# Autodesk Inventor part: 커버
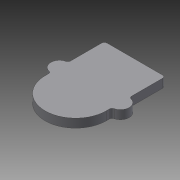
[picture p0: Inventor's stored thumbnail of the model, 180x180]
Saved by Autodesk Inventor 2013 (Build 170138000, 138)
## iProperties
Created: 2024-02
Part Number: 커버
Material: 알루미늄 6061
Document SubType Name: Modeling
Designer: mdu-01
Density: 1 g/cm^3
Author: mdu-01
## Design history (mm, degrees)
sketch "스케치1"
  geometry: L1 (14, -3.702)-(14, -14.074) reference; L2 (-14, -14.074)-(-14, -3.702) reference; L3 (35, 3.761)-(35, 39.612) reference; L4 (32, 42.612)-(-32, 42.612) reference; L5 (-35, 39.612)-(-35, 3.761) reference; L6 (-35, -21.537)-(-35, -25.388) reference; L7 (35, -25.388)-(35, -21.537) reference; C1 r 2.75 at (0, -51.388) reference; C2 r 2.75 at (-35, -8.888) reference; C3 r 2.75 at (35, -8.888) reference; C4 r 2.75 at (0, 33.612) reference; A1 r 18 centre (0, 7.612) between (14, -3.702) and (-14, -3.702) reference; A2 r 18 centre (0, -25.388) between (-14, -14.074) and (14, -14.074) reference; A3 r 3 centre (38, 3.761) between (35, 3.761) and (37.308, 0.842) reference; A4 r 3 centre (32, 39.612) between (35, 39.612) and (32, 42.612) reference; A5 r 3 centre (-32, 39.612) between (-32, 42.612) and (-35, 39.612) reference; A6 r 3 centre (-38, 3.761) between (-37.308, 0.842) and (-35, 3.761) reference; A7 r 10 centre (-35, -8.888) between (-37.308, 0.842) and (-37.308, -18.618) reference; A8 r 3 centre (-38, -21.537) between (-35, -21.537) and (-37.308, -18.618) reference; A9 r 35 centre (0, -25.388) between (-35, -25.388) and (35, -25.388) reference; A10 r 3 centre (38, -21.537) between (37.308, -18.618) and (35, -21.537) reference; A11 r 10 centre (35, -8.888) between (37.308, -18.618) and (37.308, 0.842) reference; 1 further point
extrude "돌출1" new body sketch "스케치1" distance "d0" = 10; taper "d1" = 0 deg
sketch "스케치2"
  geometry: L1 (-15, 7.612)-(-15, -25.388); L2 (15, 7.612)-(15, -25.388); A1 r 15 centre (0, -25.388) between (-15, -25.388) and (15, -25.388); A2 r 15 centre (0, 7.612) between (15, 7.612) and (-15, 7.612); 3 further points
  constraints: 4 end point, 4 point on circle, 4 tangent, 2 centre point, 2 coincident
  dimensions: "d2" = 30 diameter of A1; "d3" = 30 diameter of A2
extrude "돌출2" join sketch "스케치2" distance "d4" = 9; taper "d5" = 0 deg
fillet "모깎기1" dims "d6" = 3
sketch "스케치3"
  geometry: L1 (-25.388, 0)-(-25.388, 14.041); L2 (-25.388, 16)-(-25.388, 19) reference; L3 (-25.388, 14.041)-(-18.388, 10); L4 (-18.388, 10)-(-15.388, 10); L5 (-15.388, 10)-(-15.388, 0); L6 (0.842, 0)-(-18.618, 0) reference; L7 (-15.388, 0)-(-25.388, 0); 2 further points
  constraints: 10 end point, 2 collinear, 1 parallel, 1 point on line
  dimensions: "d7" = 10 distance between parallel lines of L4 L7; "d9" = 14 diameter of L3.end L1; "d10" = 60 deg angle of L1 L3; "d11" = 20 diameter of L5 L1
revolve "회전1" sketch "스케치3" stored, may be unused: angle "d12" = 90 deg
chamfer "모따기1" distance "d13" = 1; stored, may be unused: second distance "d14" = 2, angle "d15" = 45 deg
sketch "스케치4"
  geometry: 5 further points
hole "구멍1" sketch "스케치4" at (35, -8.888), (-35, -8.888), (0, 33.612), (0, -51.388) diameter "d19" = 5.5; stored, may be unused: countersink angle "d23" = 90 deg, drill point angle "d25" = 118 deg; dims "d20" = 6, "d21" = 10, "d22" = 5.5, "d24" = 8
node "솔리드1"
pattern_linear "직사각형 패턴1" dims "d18" = 33
node "참조1"
